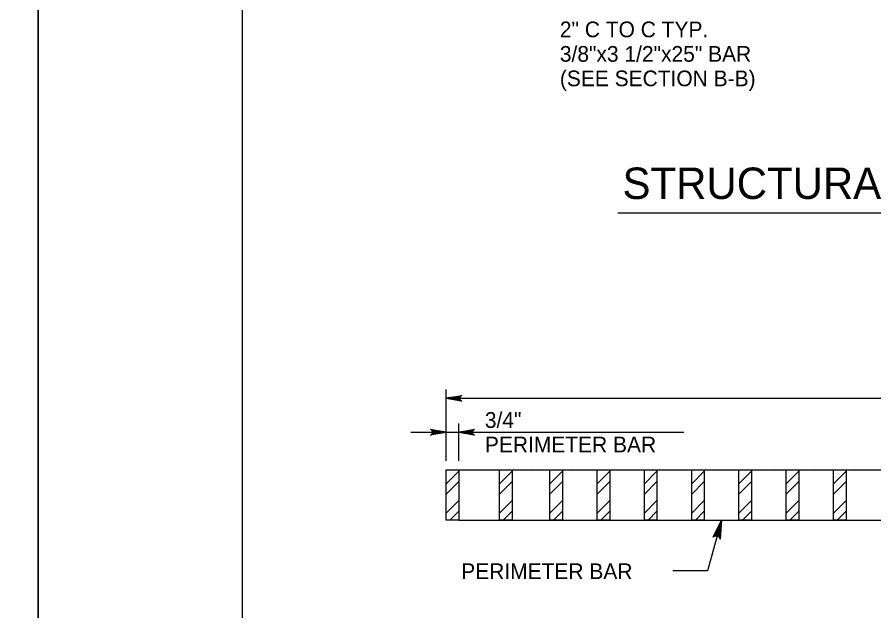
# Model space of a CAD drawing. Extents: x 2087776 to 2104538, y 970919 to 982612.
# Drawn here: x 2096040 to 2096578, y 979622 to 979995 of the extents above; entities that cross this region are included whole.
import ezdxf

# ---------------------------------------------------------------- set-up
doc = ezdxf.new("R2010")
doc.units = 0
doc.layers.add('1', color=7, linetype='Continuous')
doc.layers.add('PLT-BNDY', color=7, linetype='Continuous')

msp = doc.modelspace()

# ---------------------------------------------------------------- linework, layer by layer
at = {"layer": '1'}
for p, q in [((2096417.07, 979871.89), (2096846.17, 979871.89)), ((2096309.27, 979716.36), (2096309.27, 979761.18)), ((2096309.27, 979755.67), (2097009.03, 979755.67)), ((2096309.27, 979716.36), (2096309.27, 979739.89)), ((2096317.14, 979716.36), (2096317.14, 979739.89)), ((2096286.96, 979734.38), (2096458.34, 979734.38)), ((2096309.27, 979679.35), (2096309.27, 979710.85)), ((2096317.14, 979710.85), (2097009.03, 979710.85)), ((2096342.68, 979679.35), (2096342.68, 979710.85)), ((2096374.32, 979679.35), (2096374.32, 979710.85)), ((2096403.99, 979679.35), (2096403.99, 979710.85)), ((2096433.66, 979679.35), (2096433.66, 979710.85)), ((2096463.33, 979679.35), (2096463.33, 979710.85)), ((2096493, 979679.35), (2096493, 979710.85)), ((2096522.68, 979679.35), (2096522.68, 979710.85)), ((2096552.35, 979679.35), (2096552.35, 979710.85)), ((2096317.14, 979679.35), (2097009.03, 979679.35)), ((2096482.06, 979679.35), (2096473.29, 979647.4))]:
    msp.add_line(p, q, dxfattribs=at)
for points in [[(2098759.93, 978763.82), (2098759.93, 980614.22), (2096181.19, 980614.22), (2096181.19, 978763.82), (2098759.93, 978763.82), (2098759.93, 978850.3), (2098103.76, 978850.3), (2098103.76, 979062.5), (2098759.93, 979062.5), (2098759.93, 979157.53), (2098103.76, 979157.53), (2098103.76, 978763.82), (2098362.29, 978763.82), (2098362.29, 978850.3), (2098362.29, 978763.82), (2098614.92, 978763.82), (2098614.92, 978850.3), (2098614.92, 978809.9), (2098759.93, 978809.9)], [(2096309.27, 979755.67), (2096319.06, 979757.5), (2096318.68, 979757.24), (2096318.3, 979756.98), (2096318.11, 979756.65), (2096317.91, 979756.32), (2096317.86, 979756), (2096317.8, 979755.67), (2096317.86, 979755.34), (2096317.91, 979755.01), (2096318.11, 979754.68), (2096318.3, 979754.36), (2096318.68, 979754.09), (2096319.06, 979753.83), (2096309.27, 979755.67), (2096318.68, 979754.09), (2096318.3, 979754.36), (2096309.27, 979755.67), (2096318.11, 979754.68), (2096317.91, 979755.01), (2096309.27, 979755.67), (2096317.86, 979755.34), (2096317.8, 979755.67), (2096309.27, 979755.67), (2096317.86, 979756), (2096317.91, 979756.32), (2096309.27, 979755.67), (2096318.11, 979756.65), (2096318.3, 979756.98), (2096309.27, 979755.67), (2096318.68, 979757.24)], [(2096309.27, 979734.38), (2096299.48, 979732.54), (2096299.86, 979732.8), (2096300.24, 979733.06), (2096300.43, 979733.39), (2096300.63, 979733.72), (2096300.68, 979734.05), (2096300.74, 979734.38), (2096300.68, 979734.7), (2096300.63, 979735.03), (2096300.43, 979735.36), (2096300.24, 979735.69), (2096299.86, 979735.95), (2096299.48, 979736.21), (2096309.27, 979734.38), (2096299.86, 979735.95), (2096300.24, 979735.69), (2096309.27, 979734.38), (2096300.43, 979735.36), (2096300.63, 979735.03), (2096309.27, 979734.38), (2096300.68, 979734.7), (2096300.74, 979734.38), (2096309.27, 979734.38), (2096300.68, 979734.05), (2096300.63, 979733.72), (2096309.27, 979734.38), (2096300.43, 979733.39), (2096300.24, 979733.06), (2096309.27, 979734.38), (2096299.86, 979732.8)], [(2096317.14, 979734.38), (2096326.93, 979736.21), (2096326.55, 979735.95), (2096326.18, 979735.69), (2096325.98, 979735.36), (2096325.79, 979735.03), (2096325.73, 979734.7), (2096325.67, 979734.38), (2096325.73, 979734.05), (2096325.79, 979733.72), (2096325.98, 979733.39), (2096326.18, 979733.06), (2096326.55, 979732.8), (2096326.93, 979732.54), (2096317.14, 979734.38), (2096326.55, 979732.8), (2096326.18, 979733.06), (2096317.14, 979734.38), (2096325.98, 979733.39), (2096325.79, 979733.72), (2096317.14, 979734.38), (2096325.73, 979734.05), (2096325.67, 979734.38), (2096317.14, 979734.38), (2096325.73, 979734.7), (2096325.79, 979735.03), (2096317.14, 979734.38), (2096325.98, 979735.36), (2096326.18, 979735.69), (2096317.14, 979734.38), (2096326.55, 979735.95)], [(2096309.27, 979710.45), (2096309.66, 979710.85)], [(2096309.27, 979702.1), (2096317.14, 979709.97)], [(2096342.68, 979710.45), (2096343.07, 979710.85)], [(2096342.68, 979702.1), (2096350.55, 979709.97)], [(2096362.89, 979710.45), (2096363.29, 979710.85)], [(2096374.32, 979702.1), (2096382.19, 979709.97)], [(2096388.23, 979710.45), (2096388.62, 979710.85)], [(2096403.99, 979702.1), (2096411.86, 979709.97)], [(2096413.55, 979710.45), (2096413.95, 979710.85)], [(2096433.66, 979702.1), (2096441.53, 979709.97)], [(2096438.89, 979710.45), (2096439.28, 979710.85)], [(2096463.33, 979702.1), (2096471.21, 979709.97)], [(2096464.22, 979710.45), (2096464.62, 979710.85)], [(2096489.56, 979710.45), (2096489.95, 979710.85)], [(2096493, 979702.1), (2096500.88, 979709.97)], [(2096514.89, 979710.45), (2096515.29, 979710.85)], [(2096522.68, 979702.1), (2096530.55, 979709.97)], [(2096540.23, 979710.45), (2096540.62, 979710.85)], [(2096552.35, 979702.1), (2096560.22, 979709.97)], [(2096565.56, 979710.45), (2096565.96, 979710.85)], [(2096309.27, 979695.61), (2096317.14, 979703.48)], [(2096342.68, 979695.61), (2096350.55, 979703.48)], [(2096374.32, 979695.61), (2096382.19, 979703.48)], [(2096403.99, 979695.61), (2096411.86, 979703.48)], [(2096433.66, 979695.61), (2096441.53, 979703.48)], [(2096463.33, 979695.61), (2096471.21, 979703.48)], [(2096493, 979695.61), (2096500.88, 979703.48)], [(2096522.68, 979695.61), (2096530.55, 979703.48)], [(2096552.35, 979695.61), (2096560.22, 979703.48)], [(2096309.27, 979683.62), (2096317.14, 979691.5)], [(2096342.68, 979683.62), (2096350.55, 979691.5)], [(2096374.32, 979683.62), (2096382.19, 979691.5)], [(2096403.99, 979683.62), (2096411.86, 979691.5)], [(2096433.66, 979683.62), (2096441.53, 979691.5)], [(2096463.33, 979683.62), (2096471.21, 979691.5)], [(2096493, 979683.62), (2096500.88, 979691.5)], [(2096522.68, 979683.62), (2096530.55, 979691.5)], [(2096552.35, 979683.62), (2096560.22, 979691.5)], [(2096311.57, 979679.35), (2096317.14, 979684.92)], [(2096344.98, 979679.35), (2096350.55, 979684.92)], [(2096376.62, 979679.35), (2096382.19, 979684.92)], [(2096406.29, 979679.35), (2096411.86, 979684.92)], [(2096435.96, 979679.35), (2096441.53, 979684.92)], [(2096465.64, 979679.35), (2096471.21, 979684.92)], [(2096495.31, 979679.35), (2096500.88, 979684.92)], [(2096524.98, 979679.35), (2096530.55, 979684.92)], [(2096554.65, 979679.35), (2096560.22, 979684.92)], [(2096482.06, 979679.35), (2096481.14, 979667.37), (2096480.95, 979667.89), (2096480.77, 979668.41), (2096480.44, 979668.74), (2096480.12, 979669.07), (2096479.76, 979669.24), (2096479.39, 979669.4), (2096478.99, 979669.44), (2096478.59, 979669.48), (2096478.15, 979669.35), (2096477.71, 979669.23), (2096477.28, 979668.87), (2096476.86, 979668.51), (2096482.06, 979679.35), (2096477.28, 979668.87), (2096477.71, 979669.23), (2096482.06, 979679.35), (2096478.15, 979669.35), (2096478.59, 979669.48), (2096482.06, 979679.35), (2096478.99, 979669.44), (2096479.39, 979669.4), (2096482.06, 979679.35), (2096479.76, 979669.24), (2096480.12, 979669.07), (2096482.06, 979679.35), (2096480.44, 979668.74), (2096480.77, 979668.41), (2096482.06, 979679.35), (2096480.95, 979667.89)], [(2096473.29, 979647.4), (2096451.51, 979647.4)]]:
    msp.add_lwpolyline(points, dxfattribs=at)
for points in [[(2096309.27, 979679.35), (2096309.27, 979710.85), (2096317.14, 979710.85), (2096317.14, 979679.35)], [(2096342.68, 979679.35), (2096342.68, 979710.85), (2096350.55, 979710.85), (2096350.55, 979679.35)], [(2096374.32, 979679.35), (2096374.32, 979710.85), (2096382.19, 979710.85), (2096382.19, 979679.35)], [(2096403.99, 979679.35), (2096403.99, 979710.85), (2096411.86, 979710.85), (2096411.86, 979679.35)], [(2096433.66, 979679.35), (2096433.66, 979710.85), (2096441.53, 979710.85), (2096441.53, 979679.35)], [(2096463.33, 979679.35), (2096463.33, 979710.85), (2096471.21, 979710.85), (2096471.21, 979679.35)], [(2096493, 979679.35), (2096493, 979710.85), (2096500.88, 979710.85), (2096500.88, 979679.35)], [(2096522.68, 979679.35), (2096522.68, 979710.85), (2096530.55, 979710.85), (2096530.55, 979679.35)], [(2096552.35, 979679.35), (2096552.35, 979710.85), (2096560.22, 979710.85), (2096560.22, 979679.35)]]:
    msp.add_lwpolyline(points, close=True, dxfattribs=at)
at = {"layer": 'PLT-BNDY'}
for points in [[(2093294.05, 980663.43), (2096053.23, 980663.43), (2096053.23, 978714.61), (2093294.05, 978714.61)], [(2096053.23, 980663.43), (2098812.42, 980663.43), (2098812.42, 978714.61), (2096053.23, 978714.61)]]:
    msp.add_lwpolyline(points, close=True, dxfattribs=at)

# ---------------------------------------------------------------- texts
at = {"layer": '1'}
for s, height, p in [('2" C TO C TYP.', 9.8425, (2096380.58, 979982.02)), ('3/8"x3 1/2"x25" BAR', 9.8425, (2096380.58, 979966.66)), ('(SEE SECTION B-B)', 9.8425, (2096380.58, 979951.31)), ('STRUCTURAL STEEL GRATE', 19.685, (2096419.92, 979880.64)), ('3/4"', 9.843, (2096333.51, 979737.12)), ('PERIMETER BAR', 9.8425, (2096333.51, 979721.76)), ('PERIMETER BAR', 9.8425, (2096318.66, 979642.31))]:
    msp.add_text(s, height=height, dxfattribs=at).set_placement(p)

doc.saveas('drawing.dxf')
